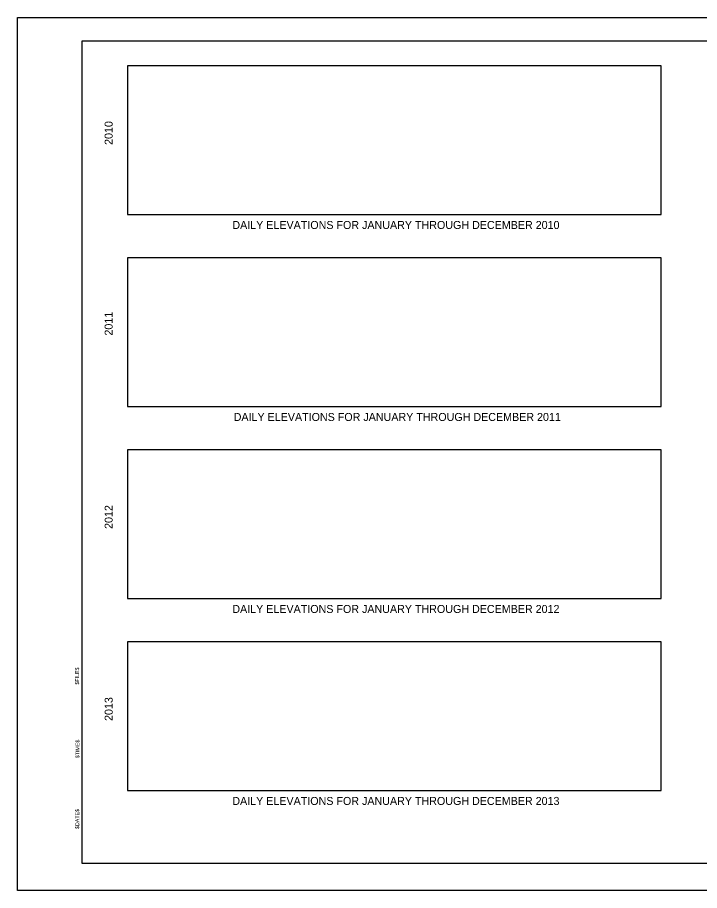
# Model space of a CAD drawing. Extents: x -1063117.8 to -1063083.7, y -253323.4 to -253301.6.
# Drawn here: x -1063117.78 to -1063100.74, y -253323.44 to -253301.63 of the extents above; entities that cross this region are included whole.
import ezdxf

# ---------------------------------------------------------------- set-up
doc = ezdxf.new("R2010")
doc.units = 0
for name, color, linetype in [('border', 7, 'Continuous'), ('Dimensions', 7, 'Continuous'), ('Level 62', 7, 'Continuous'), ('Title Text', 7, 'Continuous')]:
    doc.layers.add(name, color=color, linetype=linetype)

msp = doc.modelspace()

# ---------------------------------------------------------------- linework, layer by layer
at = {"layer": 'border'}
for p, q in [((-1063116.157, -253302.216), (-1063084.146, -253302.216)), ((-1063116.157, -253322.761), (-1063116.157, -253302.216)), ((-1063084.146, -253322.761), (-1063116.157, -253322.761))]:
    msp.add_line(p, q, dxfattribs=at)
at = {"layer": 'Dimensions'}
for points in [[(-1063115.028, -253306.552), (-1063101.694, -253306.552), (-1063101.694, -253302.836), (-1063115.028, -253302.836)], [(-1063115.027, -253311.348), (-1063101.694, -253311.348), (-1063101.694, -253307.632), (-1063115.027, -253307.632)], [(-1063115.027, -253316.144), (-1063101.694, -253316.144), (-1063101.694, -253312.428), (-1063115.027, -253312.428)], [(-1063115.027, -253320.94), (-1063101.693, -253320.94), (-1063101.693, -253317.224), (-1063115.027, -253317.224)]]:
    msp.add_lwpolyline(points, close=True, dxfattribs=at)
at = {"layer": 'Level 62'}
msp.add_lwpolyline([(-1063117.777, -253301.63), (-1063083.659, -253301.63), (-1063083.659, -253323.44), (-1063117.777, -253323.44)], close=True, dxfattribs=at)

# ---------------------------------------------------------------- texts
at = {"layer": 'border'}
for s, p in [('$FILE$', (-1063116.24, -253318.295)), ('$TIME$', (-1063116.23, -253320.136)), ('$DATE$', (-1063116.234, -253321.903))]:
    msp.add_text(s, height=0.096, rotation=89.9999, dxfattribs=at).set_placement(p)
at = {"layer": 'Title Text'}
for s, p in [('2010', (-1063115.399, -253304.814)), ('2011', (-1063115.399, -253309.577)), ('2012', (-1063115.398, -253314.407)), ('2013', (-1063115.398, -253319.204))]:
    msp.add_text(s, height=0.2, rotation=90, dxfattribs=at).set_placement(p)
for s, p in [(' DAILY ELEVATIONS FOR JANUARY THROUGH DECEMBER 2010 ', (-1063112.482, -253306.914)), (' DAILY ELEVATIONS FOR JANUARY THROUGH DECEMBER 2011 ', (-1063112.449, -253311.71)), (' DAILY ELEVATIONS FOR JANUARY THROUGH DECEMBER 2012 ', (-1063112.483, -253316.506)), (' DAILY ELEVATIONS FOR JANUARY THROUGH DECEMBER 2013 ', (-1063112.483, -253321.302))]:
    msp.add_text(s, height=0.2, dxfattribs=at).set_placement(p)

doc.saveas('drawing.dxf')
